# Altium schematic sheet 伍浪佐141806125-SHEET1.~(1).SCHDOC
size A4; danweimingcheng: 江门职业技术学院; banbie: 14电路设计1班; xingming: 伍浪佐; xuehao: 141806125; tuming: 语音放大器; wenjianming: 语音放大器原理图; gongyifu: 共  1  幅
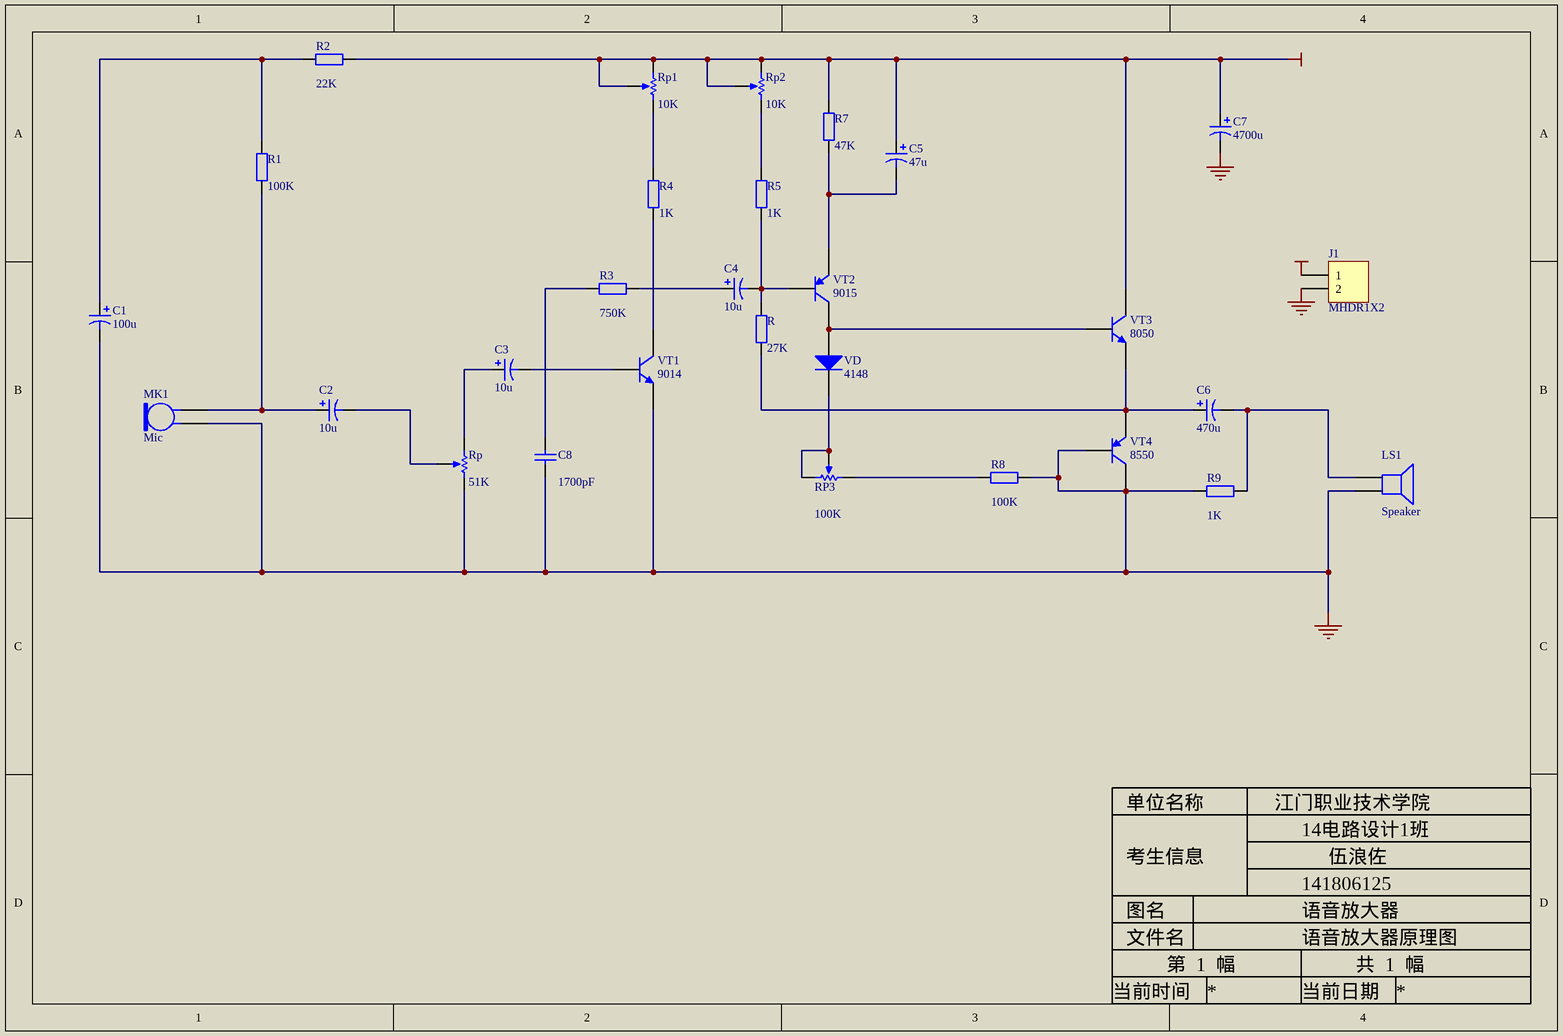
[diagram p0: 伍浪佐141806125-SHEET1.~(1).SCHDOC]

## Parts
C1  100u  [RB7.6-15]
C2  10u  [RB7.6-15]
C3  10u  [RB7.6-15]
C4  10u  [RB7.6-15]
C5  47u  [RB7.6-15]
C6  470u  [RB7.6-15]
C7  4700u  [RB7.6-15]
C8  value 1700pF  [RAD-0.3]  (hidden comment: Cap)
J1  MHDR1X2  [MHDR1X2]
LS1  Speaker  [PIN2]
MK1  Mic  [PIN2]
R  value 27K  [AXIAL-0.4]  (hidden comment: Res2)
R1  value 100K  [AXIAL-0.4]  (hidden comment: Res2)
R2  value 22K  [AXIAL-0.4]  (hidden comment: Res2)
R3  value 750K  [AXIAL-0.4]  (hidden comment: Res2)
R4  value 1K  [AXIAL-0.4]  (hidden comment: Res2)
R5  value 1K  [AXIAL-0.4]  (hidden comment: Res2)
R7  value 47K  [AXIAL-0.4]  (hidden comment: Res2)
R8  value 100K  [AXIAL-0.4]  (hidden comment: Res2)
R9  value 1K  [AXIAL-0.4]  (hidden comment: Res2)
Rp  value 51K  [VR5]  (hidden comment: RPot)
Rp1  value 10K  [VR5]  (hidden comment: RPot)
Rp2  value 10K  [VR5]  (hidden comment: RPot)
RP3  value 100K  [VR5]  (hidden comment: RPot)
VD  4148  [DSO-C2/X3.3]
VT1  9014  [BCY-W3]
VT2  9015  [BCY-W3/E4]
VT3  8050  [BCY-W3/E4]
VT4  8550  [BCY-W3/E4]

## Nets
GND: C1.2 C7.2 C8.1 J1.2 LS1.2 MK1.1 R8.2 R9.1 Rp.2(BOT) VT1.3(E) VT4.2(B) VT4.3(C)
VCC: C5.1 C7.1 J1.1 R2.2 R7.2 Rp1.1(TOP) Rp1.3(TAP) Rp2.1(TOP) Rp2.3(TAP) VT3.3(C)
NetC1_1: C1.1 R1.2 R2.1
NetC2_1: C2.1 MK1.2 R1.1
NetC2_2: C2.2 Rp.3(TAP)
NetC3_1: C3.1 Rp.1(TOP)
NetC3_2: C3.2 VT1.2(B)
NetC4_1: C4.1 R3.2
NetC4_2: C4.2 R.2 R5.1 VT2.2(B)
NetC5_2: C5.2 R7.1 VT2.1(E)
NetC6_1: C6.1 R.1 VT3.1(E) VT4.1(E)
NetC6_2: C6.2 LS1.1 R9.2
NetC8_2: C8.2 R3.1
NetR4_1: R4.1 VT1.1(C)
NetR4_2: R4.2 Rp1.2(BOT)
NetR5_2: R5.2 Rp2.2(BOT)
NetR8_1: R8.1 RP3.1(TOP)
NetRP3_2: RP3.2(BOT) RP3.3(TAP) VD.2(K)
NetVD_1: VD.1(A) VT2.3(C) VT3.2(B)

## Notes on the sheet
- 单位名称
- 考生信息
- 图名
- 文件名
- 第  1  幅
- 当前时间
- 当前日期

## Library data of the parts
C1-C7 = Cap Pol1: Polarized Capacitor (Radial); Value: 100pF
C8 = Cap: Capacitor
J1 = MHDR1X2: Header, 2-Pin
LS1 = Speaker: Loudspeaker
MK1 = Mic2: Microphone
R R1-R5 R7-R9 = Res2: Resistor
Rp Rp1 Rp2 RP3 = RPot: Potentiometer; Sim Note: Enter the Resistance value and the set point into parameter fields.; Set Position: 0.5
VD = Diode: Default Diode
VT1 = NPN: NPN Bipolar Transistor
VT2 VT4 = 2N3906: PNP General Purpose Amplifier
VT3 = 2N3904: NPN General Purpose Amplifier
